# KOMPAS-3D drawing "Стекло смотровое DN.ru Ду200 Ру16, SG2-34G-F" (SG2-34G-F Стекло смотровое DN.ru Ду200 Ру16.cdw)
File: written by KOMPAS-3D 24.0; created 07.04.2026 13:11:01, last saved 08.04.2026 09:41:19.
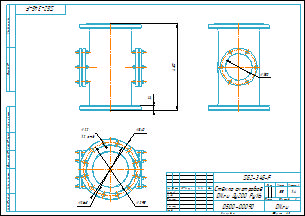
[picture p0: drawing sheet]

Document properties: Автор: Main; Форматы листов документа: A3; Полное имя файла: SG2-34G-F Стекло смотровое DN.ru Ду200 Ру16.m3d; Масса: 55; Наименование: Стекло смотровое DN.ru Ду200 Ру16; Количество листов документа: 1; Примечание: D500-00090

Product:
- Part/product: Стекло смотровое DN.ru Ду200 Ру16  | designation SG2-34G-F
    Масса: 55
    Раздел спецификации: Прочие изделия
    Примечание: D500-00090

Views: Вид 1, Снизу, Проекционный вид 2, Проекционный вид 3
Referenced files in D:\DN.ru Аутсерс\Стекло смотровое DN.ru\Стекло смотровое DN.ru SG2-34G-F тип В ГОСТ 21836-2021 Ду100 Ру16, углеродистая сталь, фланцевое\: SG2-34G-F тип В Стекло смотровое DN.ru Ду100 Ру16.m3d, SG2-34G-F тип ВСтекло смотровое DN.ru Ду100 Ру16.cdw
Referenced files in D:\DN.ru Аутсерс\Стекло смотровое DN.ru\SG2-34G-F Стекло смотровое DN.ru Ду200 Ру16\: SG2-34G-F Стекло смотровое DN.ru Ду200 Ру16.m3d
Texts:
  SG2-34G-F
  Стекло смотровое
  DN.ru Ду200 Ру16
  Стекло смотровое DN.ru Ду200 Ру16
  SG2-34G-F Стекло смотровое DN.ru Ду200 Ру16
Dimensions and other numbers on the sheet: 0; 3; 2; 4; 480; 24; 22; 12 отв.; 340; 295; 268; 150; 1:4; 1; 55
